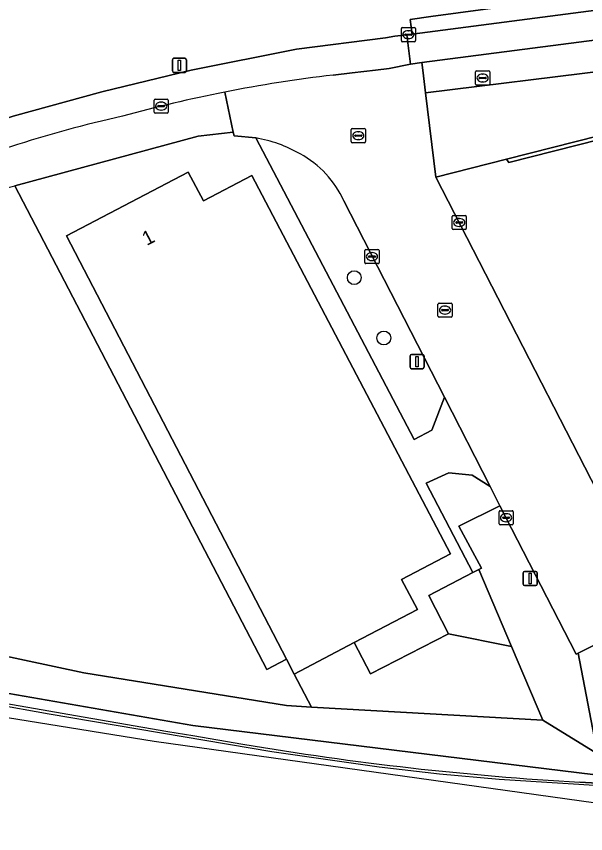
# Model space of a CAD drawing. Extents: x 160806 to 161707, y 383696 to 384148.
# Drawn here: x 160866.1 to 160906.5, y 383695.9 to 383753.8 of the extents above; entities that cross this region are included whole.
import ezdxf

# ---------------------------------------------------------------- set-up
doc = ezdxf.new("R2010")
doc.units = 0
for name, color, linetype in [('IMGEO_Boom', 7, 'Continuous'), ('IMGEO_Fietspad_open', 7, 'Continuous'), ('IMGEO_Geluidsscherm', 7, 'Continuous'), ('IMGEO_Groenvoorziening', 7, 'Continuous'), ('IMGEO_Kolk', 7, 'Continuous'), ('IMGEO_Lichtmast', 7, 'Continuous'), ('IMGEO_Muur', 7, 'Continuous'), ('IMGEO_Pand', 7, 'Continuous'), ('IMGEO_Pand_nummerreeks', 7, 'Continuous'), ('IMGEO_Rijbaan_lokaal_open', 7, 'Continuous'), ('IMGEO_Rioolput', 7, 'Continuous'), ('IMGEO_Spoorbaan_halfverhard', 7, 'Continuous'), ('IMGEO_Voetpad_open', 7, 'Continuous')]:
    doc.layers.add(name, color=color, linetype=linetype)

msp = doc.modelspace()

# ---------------------------------------------------------------- linework, layer by layer
at = {"layer": 'IMGEO_Boom'}
for centre in [(160890.095, 383735.276), (160892.194, 383730.998)]:
    msp.add_circle(centre, 0.489, dxfattribs=at)
at = {"layer": 'IMGEO_Fietspad_open'}
msp.add_lwpolyline([(160926.307, 383756.75), (160894.194, 383752.541), (160893.833, 383752.495), (160894.094, 383750.419), (160894.884, 383750.529), (160931.609, 383755.303)], dxfattribs=at)
at = {"layer": 'IMGEO_Geluidsscherm'}
msp.add_lwpolyline([(160834.211, 383710.362), (160836.985, 383709.874), (160848.234, 383707.834), (160860.524, 383705.775), (160868.443, 383704.346), (160884.251, 383701.671), (160891.851, 383700.591), (160896.138, 383700.092), (160900.372, 383699.702), (160916.184, 383698.714), (160928.13, 383698.037), (160932.094, 383697.764)], dxfattribs=at)
at = {"layer": 'IMGEO_Groenvoorziening'}
for points in [[(160849.79, 383741.85), (160852.854, 383742.604), (160856.578, 383743.467), (160861.199, 383745.212), (160865.9, 383746.727), (160872.188, 383748.46), (160878.528, 383750), (160885.997, 383751.478), (160892.307, 383752.284), (160892.98, 383752.388), (160893.833, 383752.495), (160894.194, 383752.541), (160894.066, 383753.592), (160895.526, 383753.783), (160925.691, 383757.859)], [(160883.105, 383745.188), (160894.335, 383723.808), (160895.594, 383724.469), (160896.489, 383726.796), (160889.355, 383740.715)], [(160834.192, 383723.959), (160831.033, 383721.562), (160827.545, 383718.631), (160822.776, 383712.748), (160824.684, 383712.357), (160825.386, 383713.484), (160825.871, 383713.894), (160826.633, 383714.116), (160843.597, 383711.637), (160860.024, 383709.58), (160870.902, 383707.254), (160885.285, 383704.928), (160887.055, 383704.827), (160885.836, 383707.156), (160885.285, 383708.216), (160883.901, 383707.49), (160866.007, 383741.797)], [(161000, 383705.11), (161017.812, 383705.748), (161017.796, 383706.954), (160983.268, 383705.804), (160983.265, 383705.961), (160945.396, 383704.652), (160918.821, 383703.733), (160918.795, 383703.836), (160917.974, 383703.804), (160915.971, 383703.725), (160911.759, 383711.533), (160905.971, 383708.653), (160907.351, 383701.52), (160917.77, 383699.445), (160907.216, 383700.026), (160878.632, 383703.515), (160849.795, 383708.541), (160826.302, 383712.908), (160825.547, 383712.184)], [(160906.104, 383699.5), (160918.04, 383698.804), (160925.233, 383698.384), (160925.136, 383702.425), (161000, 383705.11)]]:
    msp.add_lwpolyline(points, dxfattribs=at)
for points in [[(160907.436, 383745.322), (160922.028, 383748.942), (160921.796, 383750), (160921.433, 383751.653), (160908.189, 383750), (160895.153, 383748.373), (160895.894, 383742.401), (160900.906, 383743.686)], [(160907.502, 383745.064), (160901.057, 383743.443), (160900.906, 383743.686), (160895.894, 383742.401), (160911.759, 383711.533), (160915.971, 383703.725), (160917.974, 383703.804)], [(160899.733, 383720.468), (160898.47, 383721.274), (160896.813, 383721.442), (160895.2, 383720.702), (160898.511, 383714.365), (160898.933, 383714.586), (160899.124, 383714.686), (160897.509, 383717.649), (160900.435, 383719.099)], [(160905.971, 383708.653), (160905.831, 383708.583), (160900.435, 383719.099), (160897.509, 383717.649), (160899.124, 383714.686), (160898.933, 383714.586), (160901.259, 383709.119), (160903.485, 383703.887), (160907.351, 383701.52)], [(160898.933, 383714.586), (160898.511, 383714.365), (160895.383, 383712.731), (160896.782, 383710.023), (160901.259, 383709.119)], [(160870.902, 383707.254), (160860.024, 383709.58), (160843.597, 383711.637), (160826.633, 383714.116), (160825.871, 383713.894), (160825.386, 383713.484), (160824.684, 383712.357), (160825.547, 383712.184), (160826.302, 383712.908), (160849.795, 383708.541), (160878.632, 383703.515), (160907.216, 383700.026), (160917.77, 383699.445), (160907.351, 383701.52), (160903.485, 383703.887), (160887.055, 383704.827), (160885.285, 383704.928)], [(160903.485, 383703.887), (160901.259, 383709.119), (160896.782, 383710.023), (160891.255, 383707.194), (160890.097, 383709.395), (160885.836, 383707.156), (160887.055, 383704.827)]]:
    msp.add_lwpolyline(points, close=True, dxfattribs=at)
for centre, radius, start, end in [((160962.184, 383644.529), 152.809, 128.02304, 136.35278), ((160881.492, 383735.78), 9.545, 60.0551, 80.27378), ((160882.881, 383737.81), 7.096, 24.17018, 61.5929), ((161656.602, 388258.877), 4622.02, 259.641693, 260.354582), ((160918.479, 383916.797), 217.649, 260.39979, 266.74058)]:
    msp.add_arc(centre, radius, start, end, dxfattribs=at)
at = {"layer": 'IMGEO_Kolk'}
for p, q in [((160893.511, 383753.009), (160894.363, 383753.009)), ((160893.436, 383752.083), (160893.436, 383752.935)), ((160893.695, 383752.503), (160893.695, 383752.515)), ((160894.133, 383752.466), (160893.735, 383752.466)), ((160893.738, 383752.552), (160894.136, 383752.552)), ((160893.924, 383752.789), (160893.949, 383752.789)), ((160894.179, 383752.515), (160894.179, 383752.503)), ((160894.437, 383752.935), (160894.437, 383752.083)), ((160894.363, 383752.009), (160893.511, 383752.009)), ((160893.947, 383752.229), (160893.922, 383752.229)), ((160875.891, 383747.014), (160875.891, 383747.866)), ((160875.966, 383747.94), (160876.818, 383747.94)), ((160876.892, 383747.866), (160876.892, 383747.014)), ((160876.15, 383747.434), (160876.15, 383747.446)), ((160876.588, 383747.397), (160876.19, 383747.397)), ((160876.193, 383747.483), (160876.591, 383747.483)), ((160876.379, 383747.72), (160876.404, 383747.72)), ((160876.634, 383747.446), (160876.634, 383747.434)), ((160876.818, 383746.94), (160875.966, 383746.94)), ((160876.402, 383747.16), (160876.377, 383747.16)), ((160897.12, 383739.689), (160897.972, 383739.689)), ((160897.045, 383738.763), (160897.045, 383739.615)), ((160897.304, 383739.183), (160897.304, 383739.195)), ((160897.742, 383739.146), (160897.344, 383739.146)), ((160897.347, 383739.232), (160897.745, 383739.232)), ((160897.533, 383739.469), (160897.558, 383739.469)), ((160897.788, 383739.195), (160897.788, 383739.183)), ((160898.046, 383739.615), (160898.046, 383738.763)), ((160897.972, 383738.689), (160897.12, 383738.689)), ((160897.556, 383738.909), (160897.531, 383738.909)), ((160890.851, 383736.343), (160890.851, 383737.195)), ((160890.926, 383737.269), (160891.778, 383737.269)), ((160891.11, 383736.763), (160891.11, 383736.775)), ((160891.153, 383736.812), (160891.551, 383736.812)), ((160891.339, 383737.049), (160891.364, 383737.049)), ((160891.594, 383736.775), (160891.594, 383736.763)), ((160891.852, 383737.195), (160891.852, 383736.343)), ((160891.778, 383736.269), (160890.926, 383736.269)), ((160891.548, 383736.726), (160891.15, 383736.726)), ((160891.362, 383736.489), (160891.337, 383736.489)), ((160900.367, 383717.826), (160900.367, 383718.678)), ((160900.442, 383718.752), (160901.294, 383718.752)), ((160900.626, 383718.246), (160900.626, 383718.258)), ((160901.064, 383718.209), (160900.666, 383718.209)), ((160900.669, 383718.295), (160901.067, 383718.295)), ((160900.855, 383718.532), (160900.88, 383718.532)), ((160901.11, 383718.258), (160901.11, 383718.246)), ((160901.368, 383718.678), (160901.368, 383717.826)), ((160901.294, 383717.752), (160900.442, 383717.752)), ((160900.878, 383717.972), (160900.853, 383717.972))]:
    msp.add_line(p, q, dxfattribs=at)
for points in [[(160893.511, 383753.009), (160894.363, 383753.009)], [(160893.436, 383752.083), (160893.436, 383752.935)], [(160894.437, 383752.935), (160894.437, 383752.083)], [(160894.363, 383752.009), (160893.511, 383752.009)], [(160875.891, 383747.014), (160875.891, 383747.866)], [(160875.966, 383747.94), (160876.818, 383747.94)], [(160876.892, 383747.866), (160876.892, 383747.014)], [(160876.818, 383746.94), (160875.966, 383746.94)], [(160897.12, 383739.689), (160897.972, 383739.689)], [(160897.045, 383738.763), (160897.045, 383739.615)], [(160898.046, 383739.615), (160898.046, 383738.763)], [(160897.972, 383738.689), (160897.12, 383738.689)], [(160890.851, 383736.343), (160890.851, 383737.195)], [(160890.926, 383737.269), (160891.778, 383737.269)], [(160891.852, 383737.195), (160891.852, 383736.343)], [(160891.778, 383736.269), (160890.926, 383736.269)], [(160900.367, 383717.826), (160900.367, 383718.678)], [(160900.442, 383718.752), (160901.294, 383718.752)], [(160901.368, 383718.678), (160901.368, 383717.826)], [(160901.294, 383717.752), (160900.442, 383717.752)]]:
    msp.add_lwpolyline(points, dxfattribs=at)
for centre, radius, start, end in [((160893.513, 383752.933), 0.0765, 91.55205, 178.44795), ((160893.513, 383752.933), 0.0765, 91.55205, 178.44795), ((160894.361, 383752.933), 0.0765, 1.55205, 88.44795), ((160894.361, 383752.933), 0.0765, 1.55205, 88.44795), ((160893.735, 383752.512), 0.0403, 85.87752, 175.75265), ((160893.732, 383752.502), 0.0366, 178.93798, 274.71019), ((160894.136, 383752.509), 0.043, 264.86636, 352.45326), ((160894.14, 383752.514), 0.0386, 1.73085, 96.63898), ((160893.513, 383752.085), 0.0765, 181.55205, 268.44795), ((160893.513, 383752.085), 0.0765, 181.55205, 268.44795), ((160894.361, 383752.085), 0.0765, 271.55205, 358.44795), ((160894.361, 383752.085), 0.0765, 271.55205, 358.44795), ((160875.968, 383747.864), 0.0765, 91.55205, 178.44795), ((160875.968, 383747.864), 0.0765, 91.55205, 178.44795), ((160876.816, 383747.864), 0.0765, 1.55205, 88.44795), ((160876.816, 383747.864), 0.0765, 1.55205, 88.44795), ((160876.19, 383747.443), 0.0403, 85.87752, 175.75265), ((160876.187, 383747.433), 0.0366, 178.93798, 274.71019), ((160876.591, 383747.44), 0.043, 264.86636, 352.45326), ((160876.595, 383747.445), 0.0386, 1.73085, 96.63898), ((160875.968, 383747.016), 0.0765, 181.55205, 268.44795), ((160875.968, 383747.016), 0.0765, 181.55205, 268.44795), ((160876.816, 383747.016), 0.0765, 271.55205, 358.44795), ((160876.816, 383747.016), 0.0765, 271.55205, 358.44795), ((160897.122, 383739.613), 0.0765, 91.55205, 178.44795), ((160897.122, 383739.613), 0.0765, 91.55205, 178.44795), ((160897.97, 383739.613), 0.0765, 1.55205, 88.44795), ((160897.97, 383739.613), 0.0765, 1.55205, 88.44795), ((160897.344, 383739.192), 0.0403, 85.87752, 175.75265), ((160897.341, 383739.182), 0.0366, 178.93798, 274.71019), ((160897.745, 383739.189), 0.043, 264.86636, 352.45326), ((160897.749, 383739.194), 0.0386, 1.73085, 96.63898), ((160897.122, 383738.765), 0.0765, 181.55205, 268.44795), ((160897.122, 383738.765), 0.0765, 181.55205, 268.44795), ((160897.97, 383738.765), 0.0765, 271.55205, 358.44795), ((160897.97, 383738.765), 0.0765, 271.55205, 358.44795), ((160890.928, 383737.193), 0.0765, 91.55205, 178.44795), ((160890.928, 383737.193), 0.0765, 91.55205, 178.44795), ((160891.15, 383736.772), 0.0403, 85.87752, 175.75265), ((160891.147, 383736.762), 0.0366, 178.93798, 274.71019), ((160891.551, 383736.769), 0.043, 264.86636, 352.45326), ((160891.555, 383736.774), 0.0386, 1.73085, 96.63898), ((160891.776, 383737.193), 0.0765, 1.55205, 88.44795), ((160891.776, 383737.193), 0.0765, 1.55205, 88.44795), ((160890.928, 383736.345), 0.0765, 181.55205, 268.44795), ((160890.928, 383736.345), 0.0765, 181.55205, 268.44795), ((160891.776, 383736.345), 0.0765, 271.55205, 358.44795), ((160891.776, 383736.345), 0.0765, 271.55205, 358.44795), ((160900.444, 383718.676), 0.0765, 91.55205, 178.44795), ((160900.444, 383718.676), 0.0765, 91.55205, 178.44795), ((160900.666, 383718.255), 0.0403, 85.87752, 175.75265), ((160900.663, 383718.245), 0.0366, 178.93798, 274.71019), ((160901.067, 383718.252), 0.043, 264.86636, 352.45326), ((160901.071, 383718.257), 0.0386, 1.73085, 96.63898), ((160901.292, 383718.676), 0.0765, 1.55205, 88.44795), ((160901.292, 383718.676), 0.0765, 1.55205, 88.44795), ((160900.444, 383717.828), 0.0765, 181.55205, 268.44795), ((160900.444, 383717.828), 0.0765, 181.55205, 268.44795), ((160901.292, 383717.828), 0.0765, 271.55205, 358.44795), ((160901.292, 383717.828), 0.0765, 271.55205, 358.44795)]:
    msp.add_arc(centre, radius, start, end, dxfattribs=at)
for centre, major_axis, ratio, start_param, end_param in [((160893.923, 383752.509), (-0.387, 0.002), 0.722429, 4.712389, 7.853982), ((160893.948, 383752.509), (-0.39, 0.002), 0.717154, 1.570796, 4.712389), ((160876.378, 383747.44), (-0.387, 0.002), 0.722429, 4.712389, 7.853982), ((160876.403, 383747.44), (-0.39, 0.002), 0.717154, 1.570796, 4.712389), ((160897.532, 383739.189), (-0.387, 0.002), 0.722429, 4.712389, 7.853982), ((160897.557, 383739.189), (-0.39, 0.002), 0.717154, 1.570796, 4.712389), ((160891.338, 383736.769), (-0.387, 0.002), 0.722429, 4.712389, 7.853982), ((160891.363, 383736.769), (-0.39, 0.002), 0.717154, 1.570796, 4.712389), ((160900.854, 383718.252), (-0.387, 0.002), 0.722429, 4.712389, 7.853982), ((160900.879, 383718.252), (-0.39, 0.002), 0.717154, 1.570796, 4.712389)]:
    msp.add_ellipse(centre, major_axis=major_axis, ratio=ratio, start_param=start_param, end_param=end_param, dxfattribs=at)
at = {"layer": 'IMGEO_Lichtmast'}
for p, q in [((160877.192, 383749.93), (160877.192, 383750.73)), ((160877.192, 383750.73), (160877.192, 383749.93)), ((160877.292, 383750.83), (160878.082, 383750.83)), ((160878.082, 383750.83), (160877.292, 383750.83)), ((160878.182, 383750.73), (160878.182, 383749.93)), ((160878.182, 383749.93), (160878.182, 383750.73)), ((160878.082, 383749.83), (160877.292, 383749.83)), ((160877.292, 383749.83), (160878.082, 383749.83)), ((160894.155, 383729.821), (160894.945, 383729.821)), ((160894.945, 383729.821), (160894.155, 383729.821)), ((160894.055, 383728.921), (160894.055, 383729.721)), ((160894.055, 383729.721), (160894.055, 383728.921)), ((160895.045, 383729.721), (160895.045, 383728.921)), ((160895.045, 383728.921), (160895.045, 383729.721)), ((160894.945, 383728.821), (160894.155, 383728.821)), ((160894.155, 383728.821), (160894.945, 383728.821)), ((160902.079, 383713.543), (160902.079, 383714.343)), ((160902.079, 383714.343), (160902.079, 383713.543)), ((160902.179, 383714.443), (160902.969, 383714.443)), ((160902.969, 383714.443), (160902.179, 383714.443)), ((160903.069, 383714.343), (160903.069, 383713.543)), ((160903.069, 383713.543), (160903.069, 383714.343)), ((160902.969, 383713.443), (160902.179, 383713.443)), ((160902.179, 383713.443), (160902.969, 383713.443))]:
    msp.add_line(p, q, dxfattribs=at)
for points in [[(160877.612, 383750.705), (160877.762, 383750.705), (160877.762, 383749.955), (160877.612, 383749.955), (160877.612, 383750.705)], [(160894.475, 383729.696), (160894.625, 383729.696), (160894.625, 383728.946), (160894.475, 383728.946), (160894.475, 383729.696)], [(160902.499, 383714.318), (160902.649, 383714.318), (160902.649, 383713.568), (160902.499, 383713.568), (160902.499, 383714.318)]]:
    msp.add_lwpolyline(points, dxfattribs=at)
for centre, start, end in [((160877.292, 383750.73), 90, 180), ((160877.292, 383750.73), 90, 180), ((160878.082, 383750.73), 0, 90), ((160878.082, 383750.73), 360, 90), ((160877.292, 383749.93), 180, 270), ((160877.292, 383749.93), 180, 270), ((160878.082, 383749.93), 270, 0), ((160878.082, 383749.93), 270, 0), ((160894.155, 383729.721), 90, 180), ((160894.155, 383729.721), 90, 180), ((160894.945, 383729.721), 0, 90), ((160894.945, 383729.721), 360, 90), ((160894.155, 383728.921), 180, 270), ((160894.155, 383728.921), 180, 270), ((160894.945, 383728.921), 270, 0), ((160894.945, 383728.921), 270, 0), ((160902.179, 383714.343), 90, 180), ((160902.179, 383714.343), 90, 180), ((160902.969, 383714.343), 0, 90), ((160902.969, 383714.343), 360, 90), ((160902.179, 383713.543), 180, 270), ((160902.179, 383713.543), 180, 270), ((160902.969, 383713.543), 270, 0), ((160902.969, 383713.543), 270, 0)]:
    msp.add_arc(centre, 0.1, start, end, dxfattribs=at)
at = {"layer": 'IMGEO_Muur'}
msp.add_lwpolyline([(160907.502, 383745.064), (160907.436, 383745.322), (160900.906, 383743.686), (160901.057, 383743.443)], close=True, dxfattribs=at)
msp.add_lwpolyline([(160918.04, 383698.804), (160906.104, 383699.5)], dxfattribs=at)
for centre, radius, start, end in [((161656.602, 388258.877), 4622.02, 259.641693, 260.354582), ((160918.479, 383916.797), 217.649, 260.39979, 266.74058)]:
    msp.add_arc(centre, radius, start, end, dxfattribs=at)
at = {"layer": 'IMGEO_Pand'}
msp.add_lwpolyline([(160882.82, 383742.515), (160879.388, 383740.713), (160878.316, 383742.755), (160869.679, 383738.245), (160885.285, 383708.216), (160885.836, 383707.156), (160890.097, 383709.395), (160894.573, 383711.746), (160893.458, 383713.867), (160896.914, 383715.682)], close=True, dxfattribs=at)
at = {"layer": 'IMGEO_Rijbaan_lokaal_open'}
for points in [[(160888.594, 383749.646), (160889.957, 383749.804), (160891.612, 383750), (160892.582, 383750.117), (160894.094, 383750.419), (160893.833, 383752.495), (160892.98, 383752.388), (160892.307, 383752.284), (160885.997, 383751.478), (160878.528, 383750), (160872.188, 383748.46), (160865.9, 383746.727), (160861.199, 383745.212), (160856.578, 383743.467), (160852.854, 383742.604), (160849.79, 383741.85)], [(160895.894, 383742.401), (160895.153, 383748.373), (160894.95, 383750), (160894.884, 383750.529), (160894.094, 383750.419), (160892.582, 383750.117), (160891.612, 383750), (160889.957, 383749.804), (160888.594, 383749.646)], [(160880.901, 383748.43), (160881.513, 383745.603), (160881.563, 383745.324), (160883.105, 383745.188)], [(160889.355, 383740.715), (160896.489, 383726.796), (160899.733, 383720.468), (160900.435, 383719.099), (160905.831, 383708.583), (160905.971, 383708.653), (160911.759, 383711.533), (160895.894, 383742.401)]]:
    msp.add_lwpolyline(points, dxfattribs=at)
for centre, radius, start, end in [((160900.978, 383646.353), 104.032, 96.83693, 101.12745), ((160900.978, 383646.353), 104.032, 96.83693, 101.12745), ((160900.916, 383646.625), 103.754, 101.12233, 105.23172), ((160894.913, 383653.354), 95.769, 102.82369, 112.69109), ((160881.492, 383735.78), 9.545, 60.0551, 80.27378), ((160882.881, 383737.81), 7.096, 24.17018, 61.5929)]:
    msp.add_arc(centre, radius, start, end, dxfattribs=at)
at = {"layer": 'IMGEO_Rioolput'}
for p, q in [((160898.703, 383749.007), (160898.703, 383749.859)), ((160898.778, 383749.933), (160899.63, 383749.933)), ((160899.191, 383749.713), (160899.216, 383749.713)), ((160899.704, 383749.859), (160899.704, 383749.007)), ((160899.63, 383748.933), (160898.778, 383748.933)), ((160898.962, 383749.427), (160898.962, 383749.439)), ((160899.4, 383749.39), (160899.002, 383749.39)), ((160899.005, 383749.476), (160899.403, 383749.476)), ((160899.214, 383749.153), (160899.189, 383749.153)), ((160899.446, 383749.439), (160899.446, 383749.427)), ((160889.883, 383744.919), (160889.883, 383745.771)), ((160889.958, 383745.845), (160890.81, 383745.845)), ((160890.371, 383745.625), (160890.396, 383745.625)), ((160890.884, 383745.771), (160890.884, 383744.919)), ((160890.142, 383745.339), (160890.142, 383745.351)), ((160890.58, 383745.302), (160890.182, 383745.302)), ((160890.185, 383745.388), (160890.583, 383745.388)), ((160890.394, 383745.065), (160890.369, 383745.065)), ((160890.626, 383745.351), (160890.626, 383745.339)), ((160890.81, 383744.845), (160889.958, 383744.845)), ((160896.037, 383732.55), (160896.037, 383733.402)), ((160896.112, 383733.476), (160896.964, 383733.476)), ((160897.038, 383733.402), (160897.038, 383732.55)), ((160896.296, 383732.97), (160896.296, 383732.982)), ((160896.734, 383732.933), (160896.336, 383732.933)), ((160896.339, 383733.019), (160896.737, 383733.019)), ((160896.548, 383732.696), (160896.523, 383732.696)), ((160896.525, 383733.256), (160896.55, 383733.256)), ((160896.78, 383732.982), (160896.78, 383732.97)), ((160896.964, 383732.476), (160896.112, 383732.476))]:
    msp.add_line(p, q, dxfattribs=at)
for points in [[(160898.703, 383749.007), (160898.703, 383749.859)], [(160898.778, 383749.933), (160899.63, 383749.933)], [(160899.704, 383749.859), (160899.704, 383749.007)], [(160899.63, 383748.933), (160898.778, 383748.933)], [(160889.883, 383744.919), (160889.883, 383745.771)], [(160889.958, 383745.845), (160890.81, 383745.845)], [(160890.884, 383745.771), (160890.884, 383744.919)], [(160890.81, 383744.845), (160889.958, 383744.845)], [(160896.037, 383732.55), (160896.037, 383733.402)], [(160896.112, 383733.476), (160896.964, 383733.476)], [(160897.038, 383733.402), (160897.038, 383732.55)], [(160896.964, 383732.476), (160896.112, 383732.476)]]:
    msp.add_lwpolyline(points, dxfattribs=at)
for centre, radius, start, end in [((160898.78, 383749.857), 0.0765, 91.55205, 178.44795), ((160898.78, 383749.857), 0.0765, 91.55205, 178.44795), ((160899.628, 383749.857), 0.0765, 1.55205, 88.44795), ((160899.628, 383749.857), 0.0765, 1.55205, 88.44795), ((160898.78, 383749.009), 0.0765, 181.55205, 268.44795), ((160898.78, 383749.009), 0.0765, 181.55205, 268.44795), ((160899.002, 383749.436), 0.0403, 85.87752, 175.75265), ((160898.999, 383749.426), 0.0366, 178.93798, 274.71019), ((160899.403, 383749.433), 0.043, 264.86636, 352.45326), ((160899.407, 383749.438), 0.0386, 1.73085, 96.63898), ((160899.628, 383749.009), 0.0765, 271.55205, 358.44795), ((160899.628, 383749.009), 0.0765, 271.55205, 358.44795), ((160889.96, 383745.769), 0.0765, 91.55205, 178.44795), ((160889.96, 383745.769), 0.0765, 91.55205, 178.44795), ((160890.808, 383745.769), 0.0765, 1.55205, 88.44795), ((160890.808, 383745.769), 0.0765, 1.55205, 88.44795), ((160889.96, 383744.921), 0.0765, 181.55205, 268.44795), ((160889.96, 383744.921), 0.0765, 181.55205, 268.44795), ((160890.182, 383745.348), 0.0403, 85.87752, 175.75265), ((160890.179, 383745.338), 0.0366, 178.93798, 274.71019), ((160890.583, 383745.345), 0.043, 264.86636, 352.45326), ((160890.587, 383745.35), 0.0386, 1.73085, 96.63898), ((160890.808, 383744.921), 0.0765, 271.55205, 358.44795), ((160890.808, 383744.921), 0.0765, 271.55205, 358.44795), ((160896.114, 383733.4), 0.0765, 91.55205, 178.44795), ((160896.114, 383733.4), 0.0765, 91.55205, 178.44795), ((160896.962, 383733.4), 0.0765, 1.55205, 88.44795), ((160896.962, 383733.4), 0.0765, 1.55205, 88.44795), ((160896.336, 383732.979), 0.0403, 85.87752, 175.75265), ((160896.333, 383732.969), 0.0366, 178.93798, 274.71019), ((160896.737, 383732.976), 0.043, 264.86636, 352.45326), ((160896.741, 383732.981), 0.0386, 1.73085, 96.63898), ((160896.114, 383732.552), 0.0765, 181.55205, 268.44795), ((160896.114, 383732.552), 0.0765, 181.55205, 268.44795), ((160896.962, 383732.552), 0.0765, 271.55205, 358.44795), ((160896.962, 383732.552), 0.0765, 271.55205, 358.44795)]:
    msp.add_arc(centre, radius, start, end, dxfattribs=at)
for centre, major_axis, ratio, start_param, end_param in [((160899.19, 383749.433), (-0.387, 0.002), 0.722429, 4.712389, 7.853982), ((160899.215, 383749.433), (-0.39, 0.002), 0.717154, 1.570796, 4.712389), ((160890.37, 383745.345), (-0.387, 0.002), 0.722429, 4.712389, 7.853982), ((160890.395, 383745.345), (-0.39, 0.002), 0.717154, 1.570796, 4.712389), ((160896.524, 383732.976), (-0.387, 0.002), 0.722429, 4.712389, 7.853982), ((160896.549, 383732.976), (-0.39, 0.002), 0.717154, 1.570796, 4.712389)]:
    msp.add_ellipse(centre, major_axis=major_axis, ratio=ratio, start_param=start_param, end_param=end_param, dxfattribs=at)
at = {"layer": 'IMGEO_Spoorbaan_halfverhard'}
msp.add_lwpolyline([(160821.504, 383711.182), (160875.894, 383702.41), (160922.821, 383695.85), (160996.257, 383695.919), (161042.213, 383698.051), (161092.512, 383703.206), (161091.717, 383705.343), (161091.615, 383705.332), (161082.438, 383704.359), (161077.717, 383703.87), (161074.945, 383703.576), (161073.852, 383703.453), (161066.359, 383702.75), (161050.171, 383701.028), (161040.034, 383700.432), (161009.181, 383699.4), (160949.68, 383697.713), (160939.829, 383697.51), (160932.571, 383697.47), (160925.335, 383698.113), (160925.233, 383698.384), (160918.04, 383698.804), (160906.104, 383699.5)], dxfattribs=at)
for centre, radius, start, end in [((161656.602, 388258.877), 4622.02, 259.641693, 260.354582), ((160918.479, 383916.797), 217.649, 260.39979, 266.74058)]:
    msp.add_arc(centre, radius, start, end, dxfattribs=at)
at = {"layer": 'IMGEO_Voetpad_open'}
for points in [[(160931.609, 383755.303), (160894.884, 383750.529), (160894.95, 383750), (160895.153, 383748.373), (160908.189, 383750), (160921.433, 383751.653), (160921.796, 383750), (160922.028, 383748.942), (160926.276, 383750), (160938.676, 383753.139), (160959.333, 383758.368), (160960.762, 383758.727), (160971.208, 383761.353)], [(160925.691, 383757.859), (160895.526, 383753.783), (160894.066, 383753.592), (160894.194, 383752.541), (160926.307, 383756.75)], [(160879.023, 383745.307), (160881.513, 383745.603), (160880.901, 383748.43)], [(160846.58, 383736.47), (160855.249, 383737.735), (160861.812, 383740.199), (160862.69, 383740.971), (160866.007, 383741.797), (160879.023, 383745.307)]]:
    msp.add_lwpolyline(points, dxfattribs=at)
msp.add_lwpolyline([(160883.105, 383745.188), (160881.563, 383745.324), (160881.513, 383745.603), (160879.023, 383745.307), (160866.007, 383741.797), (160883.901, 383707.49), (160885.285, 383708.216), (160869.679, 383738.245), (160878.316, 383742.755), (160879.388, 383740.713), (160882.82, 383742.515), (160896.914, 383715.682), (160893.458, 383713.867), (160894.573, 383711.746), (160890.097, 383709.395), (160891.255, 383707.194), (160896.782, 383710.023), (160895.383, 383712.731), (160898.511, 383714.365), (160895.2, 383720.702), (160896.813, 383721.442), (160898.47, 383721.274), (160899.733, 383720.468), (160896.489, 383726.796), (160895.594, 383724.469), (160894.335, 383723.808)], close=True, dxfattribs=at)
for centre, radius, start, end in [((160962.184, 383644.529), 152.809, 128.02304, 136.35278), ((160900.916, 383646.625), 103.754, 101.12233, 105.23172), ((160894.913, 383653.354), 95.769, 102.82369, 112.69109)]:
    msp.add_arc(centre, radius, start, end, dxfattribs=at)

# ---------------------------------------------------------------- texts
at = {"layer": 'IMGEO_Pand_nummerreeks'}
msp.add_text('1', height=1, rotation=27.57231, dxfattribs=at).set_placement((160875.373, 383737.518))

doc.saveas('drawing.dxf')
